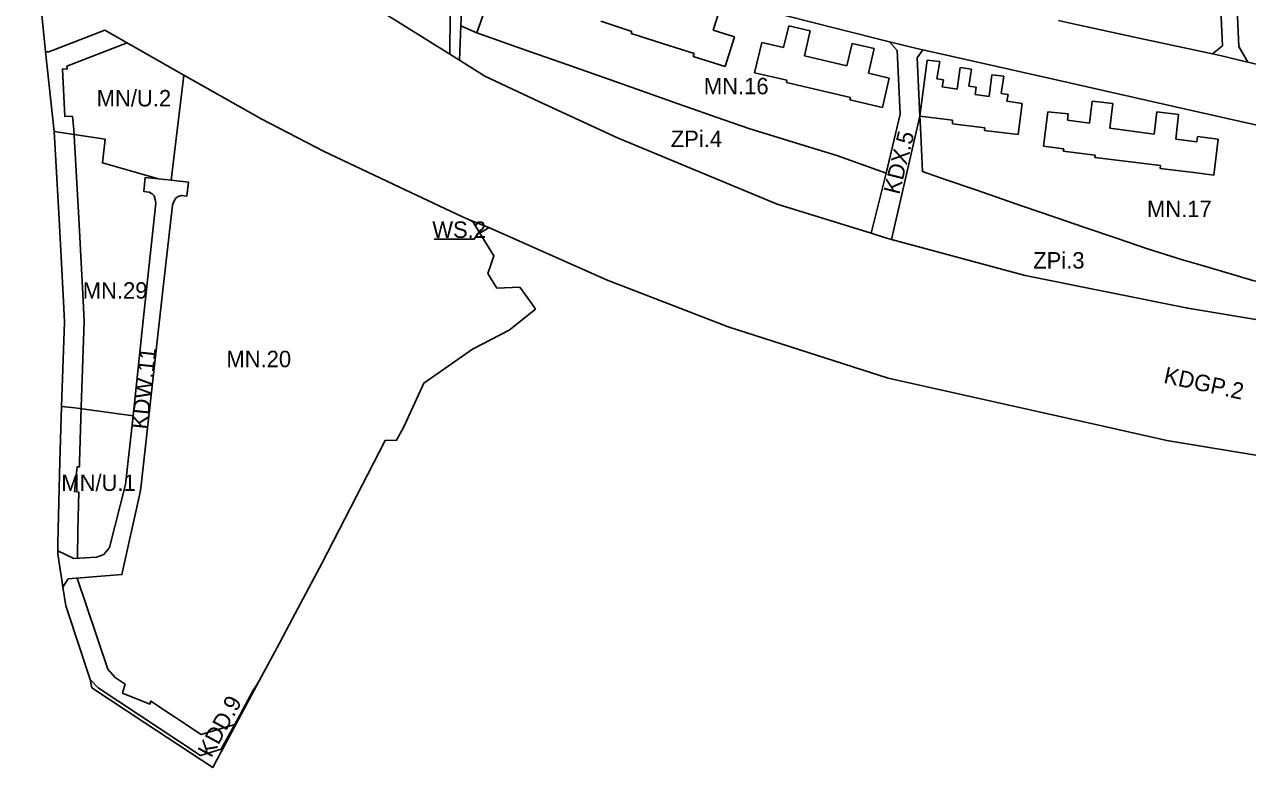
# Model space of a CAD drawing. Extents: x 7419601 to 7420547, y 5548907 to 5549873.
# Drawn here: x 7419661.1 to 7420033.1, y 5548985.8 to 5549211.8 of the extents above; entities that cross this region are included whole.
import ezdxf

# ---------------------------------------------------------------- set-up
doc = ezdxf.new("R2010")
doc.units = 0
for name, color, linetype in [('LIN_linie_rozgraniczajace', 7, 'Continuous'), ('LIN_nieprzekraczalna linia zabudowy', 7, 'Continuous'), ('LIN_obowiązująca linia zabudowy', 7, 'Continuous'), ('TXT_opisy_przeznaczen', 7, 'Continuous')]:
    doc.layers.add(name, color=color, linetype=linetype)

msp = doc.modelspace()

# ---------------------------------------------------------------- linework, layer by layer
at = {"layer": 'LIN_linie_rozgraniczajace'}
for p, q in [((7419798.71, 5549209.29), (7419793.89, 5549211.36)), ((7419667.53, 5549203.52), (7419670.21, 5549179.23)), ((7420026.14, 5549202.05), (7420030.16, 5549201.02)), ((7419709.62, 5549196.43), (7419705.73, 5549164.44)), ((7419933.5, 5549183.94), (7419924.88, 5549146.43)), ((7419923.28, 5549166.59), (7419918.69, 5549148.37)), ((7419802.98, 5549138.71), (7419802.98, 5549138.71))]:
    msp.add_line(p, q, dxfattribs=at)
for points in [[(7420022.45, 5549202.85), (7420025.54, 5549205.34), (7420023.43, 5549251.26), (7420025.54, 5549274.51), (7420027.65, 5549297.76), (7420027.03, 5549309.83), (7420026.97, 5549320.98), (7420024.81, 5549325.52)], [(7420048.72, 5549317.81), (7420035.84, 5549310.28), (7420033.75, 5549308.2), (7420032.79, 5549306.6), (7420032.47, 5549303.85), (7420032.44, 5549294.24), (7420030.96, 5549277.87), (7420028.44, 5549250.88), (7420029.48, 5549227.98), (7420030.53, 5549205.08), (7420033.23, 5549200.31)], [(7419661.15, 5549289.17), (7419671.11, 5549274.52), (7419673.17, 5549271.49), (7419736.84, 5549236.24), (7419744.84, 5549231.32), (7419790.54, 5549202.77)], [(7419809.73, 5549240.39), (7419805.23, 5549237.47), (7419797.75, 5549237.54), (7419787.92, 5549225.4), (7419787.71, 5549222.91), (7419794.15, 5549218.11), (7419793.89, 5549211.36), (7419793.48, 5549200.93)], [(7419923.28, 5549166.59), (7419908.23, 5549171.95), (7419898.64, 5549174.86), (7419889.05, 5549177.79), (7419881.72, 5549180.02), (7419873.89, 5549182.79), (7419859.94, 5549187.69), (7419850.51, 5549191.02), (7419841.07, 5549194.35), (7419826.44, 5549199.51), (7419812.76, 5549204.33), (7419798.71, 5549209.29), (7419809.73, 5549240.39)], [(7419667.53, 5549203.52), (7419665.9, 5549219.93), (7419665.75, 5549221.29)], [(7419932.6, 5549204.46), (7419924.26, 5549206.56), (7419908.56, 5549210.52), (7419884.53, 5549216.57), (7419878.14, 5549219.72), (7419875.61, 5549220.97)], [(7419790.59, 5549215.03), (7419790.54, 5549202.77)], [(7419975.63, 5549213.02), (7419979.2, 5549212.24), (7420001.06, 5549207.47), (7420022.45, 5549202.85), (7420026.14, 5549202.05)], [(7419668.54, 5549203.45), (7419685.6, 5549210.05), (7419709.62, 5549196.43), (7419733.13, 5549183.1), (7419752.26, 5549173.12), (7419773.32, 5549163.22), (7419794.39, 5549153.33)], [(7419667.53, 5549203.52), (7419668.54, 5549203.45)], [(7419923.28, 5549166.59), (7419927.47, 5549184.55), (7419926.6, 5549203.93), (7419924.26, 5549206.56)], [(7420084.89, 5549170.3), (7420078.89, 5549171.67), (7420068.95, 5549173.94), (7420058.99, 5549176.05), (7420010.3, 5549186.99), (7419973.64, 5549195.23), (7419934.39, 5549204.06), (7419932.6, 5549204.46)], [(7419934.39, 5549204.06), (7419932.71, 5549201.64), (7419933.5, 5549183.94)], [(7419790.54, 5549202.77), (7419793.48, 5549200.93)], [(7419793.48, 5549200.93), (7419801.16, 5549196.05), (7419819.36, 5549187.59), (7419841.54, 5549177.3), (7419890.05, 5549157.14), (7419918.69, 5549148.37)], [(7420030.16, 5549201.02), (7420033.23, 5549200.31), (7420054.44, 5549195.37), (7420076.37, 5549190.13), (7420079.31, 5549189.43)], [(7419933.5, 5549183.94), (7419933.66, 5549180.45), (7419934.25, 5549167.06), (7419941.13, 5549164.7), (7419950.49, 5549161.48), (7419964.74, 5549156.57), (7419974.54, 5549153.21), (7419983.67, 5549150.07), (7419993.3, 5549146.77), (7420002.76, 5549143.52), (7420013.4, 5549140.23), (7420019.71, 5549138.36), (7420025.18, 5549136.74), (7420034.78, 5549133.89), (7420046.03, 5549131.4), (7420052.08, 5549129.9), (7420061.59, 5549127.54), (7420077.26, 5549123.67)], [(7419672.44, 5549095.57), (7419673.3, 5549121.38), (7419672.98, 5549127.55), (7419671.66, 5549152.57), (7419670.21, 5549179.23)], [(7419670.21, 5549179.23), (7419685.73, 5549176.9), (7419684.87, 5549169.69), (7419701.92, 5549164.85)], [(7419672.82, 5549040.66), (7419674.44, 5549043.25), (7419690.78, 5549044.48), (7419696.35, 5549069.51), (7419696.6, 5549071.71), (7419699.46, 5549097.26), (7419703.05, 5549129.17), (7419706.15, 5549156.8), (7419706.61, 5549157.97), (7419707.15, 5549158.99), (7419707.86, 5549159.47), (7419708.87, 5549159.79), (7419710.53, 5549159.61), (7419710.99, 5549163.87), (7419705.73, 5549164.44), (7419701.92, 5549164.85), (7419697.89, 5549165.29), (7419697.44, 5549161.01), (7419699.09, 5549160.83), (7419700.02, 5549160.3), (7419700.61, 5549159.69), (7419700.93, 5549158.58), (7419701.12, 5549157.41), (7419697.47, 5549123.67), (7419694.17, 5549092.78)], [(7419794.39, 5549153.33), (7419796.7, 5549152.32), (7419802.38, 5549150.01)], [(7419799.66, 5549148.34), (7419797.64, 5549151.63), (7419796.7, 5549152.32)], [(7419802.38, 5549150.01), (7419802.24, 5549149.92), (7419799.66, 5549148.34)], [(7419802.98, 5549138.71), (7419803.91, 5549141.42), (7419799.66, 5549148.34)], [(7420308.86, 5549027.97), (7420304.45, 5549028.93), (7420221.89, 5549046.98), (7420166.67, 5549059.16), (7420119.38, 5549066.99), (7420011.67, 5549084.81), (7420008.57, 5549085.32), (7419989.25, 5549089.64), (7419923.85, 5549104.28), (7419875.2, 5549119.84), (7419838.22, 5549134.12), (7419802.38, 5549150.01)], [(7419918.69, 5549148.37), (7419922.76, 5549147), (7419924.88, 5549146.43)], [(7419924.88, 5549146.43), (7419965.46, 5549135.48), (7420014.97, 5549125.52), (7420075.91, 5549115.43)], [(7419719.42, 5548987.72), (7419732.55, 5549012.23), (7419738.68, 5549023.68), (7419742.68, 5549031.16), (7419751.63, 5549047.91), (7419770.83, 5549085.25), (7419774.31, 5549085.33), (7419776.58, 5549089.46), (7419782.61, 5549102.73), (7419797.44, 5549113.04), (7419808.59, 5549118.79), (7419816.57, 5549125.26), (7419815.53, 5549126.71), (7419811.8, 5549131.95), (7419804.77, 5549131.64), (7419802.09, 5549136.09), (7419802.98, 5549138.71)], [(7419671.28, 5549051.71), (7419671.32, 5549053.68), (7419671.42, 5549058.28), (7419671.88, 5549078.87), (7419672.44, 5549095.57)], [(7419672.44, 5549095.57), (7419676.51, 5549095.25), (7419694.17, 5549092.78)], [(7419671.28, 5549051.71), (7419676.14, 5549049.4), (7419683.04, 5549049.82), (7419685.27, 5549050.64), (7419687.05, 5549052.74), (7419691.92, 5549071.9), (7419694.17, 5549092.78)], [(7419672.82, 5549040.66), (7419672.37, 5549043.57), (7419672.12, 5549045.29), (7419671.26, 5549050.87), (7419671.28, 5549051.71)], [(7419681.17, 5549012.59), (7419674.33, 5549033.13), (7419673.69, 5549035.02), (7419672.82, 5549040.66)], [(7419681.17, 5549012.59), (7419681.68, 5549010.07), (7419697.79, 5548999.42), (7419718.4, 5548985.81), (7419719.42, 5548987.72)], [(7419681.17, 5549012.59), (7419683.59, 5549010.05), (7419714.7, 5548989.5), (7419720.93, 5548991.37)], [(7419720.93, 5548991.37), (7419726.61, 5549001.78), (7419730.63, 5549009.15), (7419731.59, 5549010.69), (7419732.55, 5549012.23)]]:
    msp.add_lwpolyline(points, dxfattribs=at)
at = {"layer": 'LIN_nieprzekraczalna linia zabudowy'}
for points in [[(7419692.35, 5549206.22), (7419674.05, 5549199.15), (7419674.14, 5549198.31), (7419672.7, 5549198.24), (7419673.4, 5549183.8), (7419675.73, 5549183.91), (7419676.19, 5549179.72)], [(7419676.19, 5549179.72), (7419677.65, 5549152.89), (7419678.97, 5549127.86), (7419679.31, 5549121.44), (7419678.43, 5549095.37)], [(7419678.43, 5549095.37), (7419677.88, 5549078.7), (7419677.84, 5549077.23), (7419677.21, 5549077.3), (7419676.41, 5549069.76), (7419677.67, 5549069.61), (7419677.42, 5549058.15), (7419677.23, 5549049.47)], [(7419677.17, 5549043.45), (7419680.02, 5549035.04), (7419686.47, 5549015.68)], [(7419686.47, 5549015.68), (7419688.71, 5549013.19), (7419691.75, 5549011.18), (7419691.09, 5549008.82), (7419691, 5549008.44), (7419699.3, 5549005.11), (7419699.54, 5549006.01), (7419714.91, 5548995.82), (7419725.47, 5548999.01)]]:
    msp.add_lwpolyline(points, dxfattribs=at)
at = {"layer": 'LIN_obowiązująca linia zabudowy'}
for p, q in [((7419870.59, 5549210.09), (7419872.91, 5549217.4)), ((7419836.45, 5549212.76), (7419845.92, 5549209.65)), ((7419893.58, 5549211.37), (7419892.03, 5549204.78)), ((7419900.13, 5549209.84), (7419893.58, 5549211.37)), ((7419845.92, 5549209.65), (7419845.71, 5549209.01)), ((7419845.71, 5549209.01), (7419855.25, 5549206)), ((7419877.15, 5549208.01), (7419870.59, 5549210.09)), ((7419874.29, 5549198.98), (7419877.15, 5549208.01)), ((7419898.35, 5549202.22), (7419900.13, 5549209.84)), ((7419855.25, 5549206), (7419864.79, 5549202.98)), ((7419864.79, 5549202.98), (7419864.5, 5549202.08)), ((7419885.37, 5549206.33), (7419883.22, 5549197.13)), ((7419892.03, 5549204.78), (7419885.37, 5549206.33)), ((7419912.91, 5549206.05), (7419911.31, 5549199.19)), ((7419919.59, 5549204.49), (7419912.91, 5549206.05)), ((7419917.84, 5549196.96), (7419919.59, 5549204.49)), ((7419864.5, 5549202.08), (7419874.29, 5549198.98)), ((7419911.31, 5549199.19), (7419898.35, 5549202.22)), ((7419935.71, 5549200.98), (7419933.5, 5549183.94)), ((7419939.58, 5549200.56), (7419935.71, 5549200.98)), ((7419938.64, 5549195.23), (7419939.58, 5549200.56)), ((7419883.22, 5549197.13), (7419893.04, 5549194.84)), ((7419924.19, 5549195.48), (7419917.84, 5549196.96)), ((7419945.7, 5549198.72), (7419944.8, 5549192.14)), ((7419949.17, 5549198.25), (7419945.7, 5549198.72)), ((7419948.36, 5549193.04), (7419949.17, 5549198.25)), ((7419955.41, 5549196.51), (7419954.51, 5549189.93)), ((7419959, 5549196.05), (7419955.41, 5549196.51)), ((7419958.25, 5549190.81), (7419959, 5549196.05)), ((7419893.04, 5549194.84), (7419892.87, 5549194.11)), ((7419892.87, 5549194.11), (7419912.35, 5549189.57)), ((7419922.11, 5549186.52), (7419924.19, 5549195.48)), ((7419940.65, 5549195.01), (7419938.64, 5549195.23)), ((7419940.31, 5549192.82), (7419940.65, 5549195.01)), ((7419944.8, 5549192.14), (7419940.31, 5549192.82)), ((7419950.57, 5549192.72), (7419948.36, 5549193.04)), ((7419950.28, 5549190.48), (7419950.57, 5549192.72)), ((7419912.35, 5549189.57), (7419912.18, 5549188.84)), ((7419912.18, 5549188.84), (7419922.11, 5549186.52)), ((7419954.51, 5549189.93), (7419950.28, 5549190.48)), ((7419960.29, 5549190.5), (7419958.25, 5549190.81)), ((7419959.94, 5549188.46), (7419960.29, 5549190.5)), ((7419964.63, 5549187.8), (7419959.94, 5549188.46)), ((7419985.91, 5549188.51), (7419985.08, 5549181.77)), ((7419992.18, 5549187.75), (7419985.91, 5549188.51)), ((7419963.42, 5549178.35), (7419964.63, 5549187.8)), ((7419972.38, 5549185.28), (7419971.06, 5549174.82)), ((7419978.6, 5549184.66), (7419972.38, 5549185.28)), ((7419978.35, 5549182.68), (7419978.6, 5549184.66)), ((7419991.29, 5549180.26), (7419992.18, 5549187.75)), ((7420005.6, 5549185.21), (7420004.76, 5549178.48)), ((7420012.17, 5549184.45), (7420005.6, 5549185.21)), ((7420011.3, 5549176.89), (7420012.17, 5549184.45)), ((7419933.5, 5549183.94), (7419943.42, 5549182.65)), ((7419943.42, 5549182.65), (7419943.37, 5549181.6)), ((7419943.37, 5549181.6), (7419953.21, 5549180.39)), ((7419985.08, 5549181.77), (7419978.35, 5549182.68)), ((7419953.21, 5549180.39), (7419953.1, 5549179.55)), ((7419953.1, 5549179.55), (7419963.42, 5549178.35)), ((7420004.76, 5549178.48), (7419991.29, 5549180.26)), ((7420017.92, 5549177.76), (7420017.76, 5549176.11)), ((7420024.26, 5549176.96), (7420017.92, 5549177.76)), ((7420022.93, 5549165.98), (7420024.26, 5549176.96)), ((7419971.06, 5549174.82), (7419977.23, 5549174.03)), ((7419977.23, 5549174.03), (7419977.1, 5549173.22)), ((7419977.1, 5549173.22), (7419986.83, 5549172.02)), ((7420017.76, 5549176.11), (7420011.3, 5549176.89)), ((7419986.83, 5549172.02), (7419986.74, 5549171.34)), ((7419986.74, 5549171.34), (7420006.67, 5549168.86)), ((7420006.67, 5549168.86), (7420006.56, 5549168.02)), ((7420006.56, 5549168.02), (7420016.82, 5549166.74)), ((7420016.82, 5549166.74), (7420022.93, 5549165.98))]:
    msp.add_line(p, q, dxfattribs=at)
at = {"layer": 'TXT_opisy_przeznaczen'}
msp.add_lwpolyline([(7419785.77, 5549146.52), (7419797.97, 5549146.52), (7419799.92, 5549149.46)], dxfattribs=at)

# ---------------------------------------------------------------- texts
for s, p in [('MN.16', (7419867.78, 5549190.57)), ('MN/U.2', (7419683.1, 5549186.88)), ('ZPi.4', (7419857.72, 5549174.51)), ('MN.17', (7420002.56, 5549153.22)), ('WS.2', (7419785.19, 5549146.9)), ('ZPi.3', (7419967.96, 5549137.56)), ('MN.29', (7419678.87, 5549128.42)), ('MN.20', (7419722.56, 5549107.57)), ('MN/U.1', (7419672.35, 5549069.93))]:
    msp.add_text(s, height=5, dxfattribs=at).set_placement(p)
for s, rotation, p in [('KDX.5', 76, (7419927.19, 5549159.86)), ('KDW.11', 84, (7419698.6, 5549088.5)), ('KDGP.2', 347.7823, (7420007.38, 5549102.85)), ('KDD.9', 61.3833, (7419717.98, 5548988.54))]:
    msp.add_text(s, height=5, rotation=rotation, dxfattribs=at).set_placement(p)

doc.saveas('drawing.dxf')
